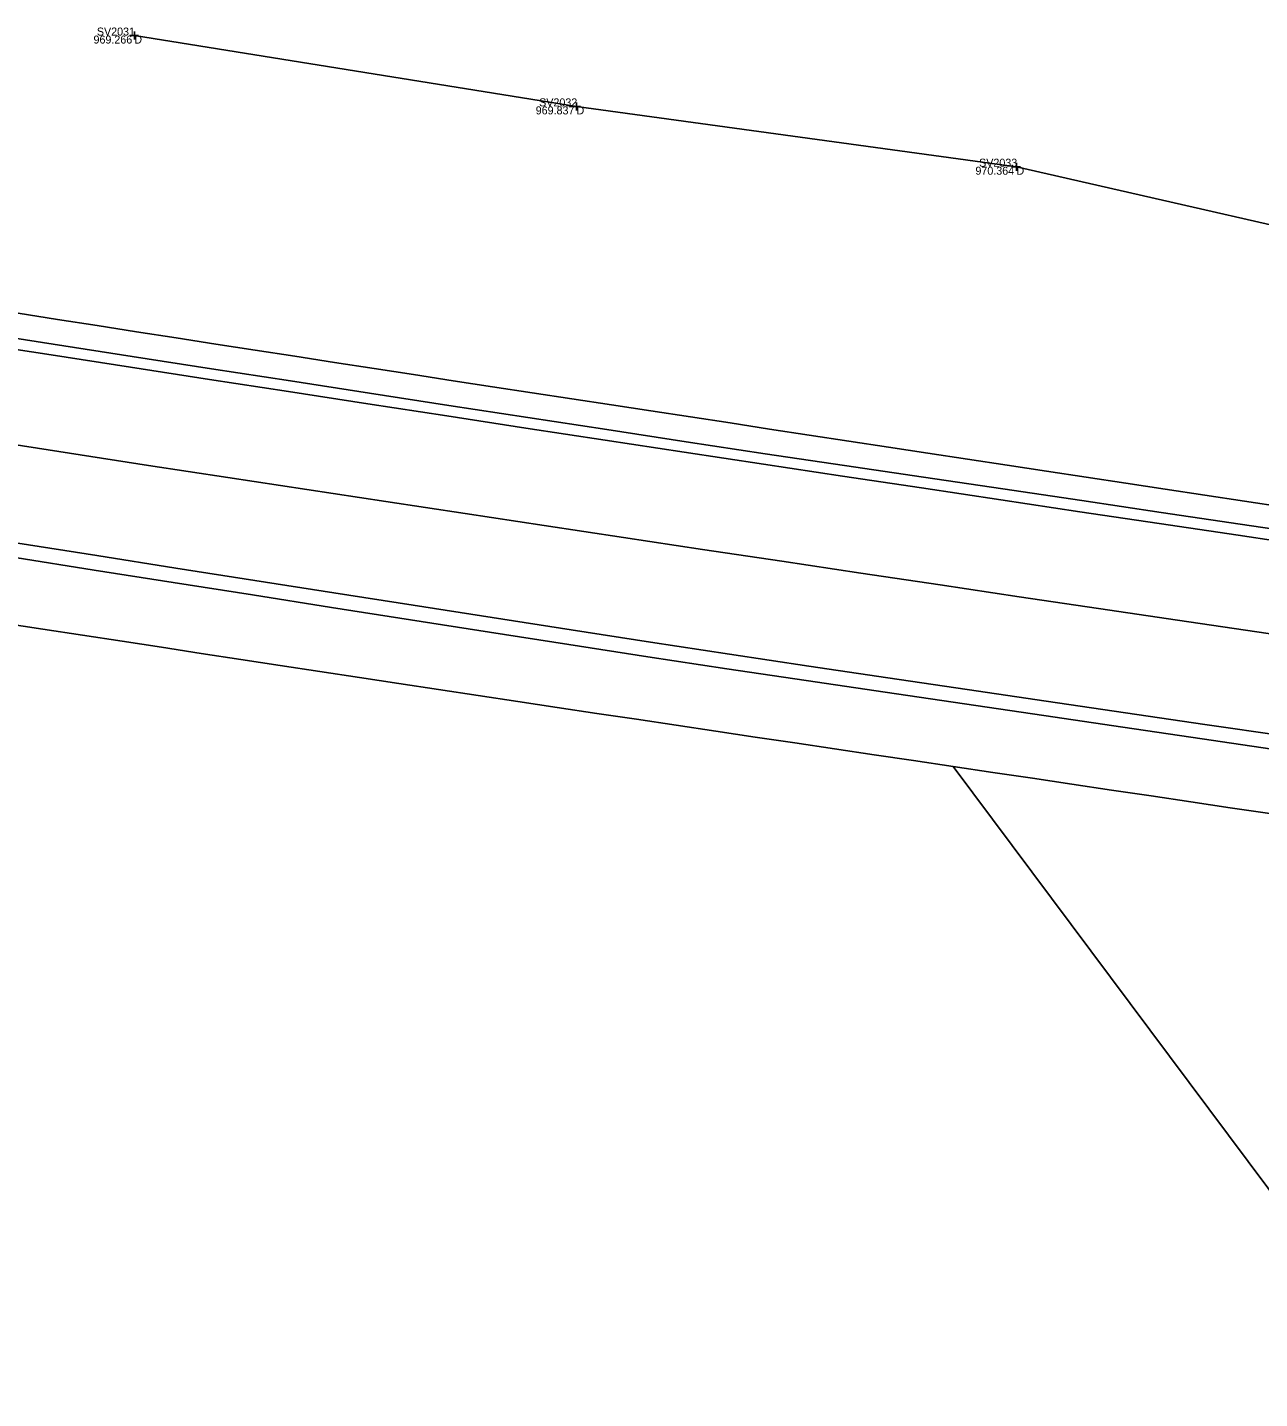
# Model space of a CAD drawing. Extents: x 2065431 to 2068157, y 709104 to 709719.
# Drawn here: x 2066132.9 to 2066286.8, y 709345.9 to 709517.3 of the extents above; entities that cross this region are included whole.
import ezdxf

# ---------------------------------------------------------------- set-up
doc = ezdxf.new("R2010")
doc.units = 0
for name, color, linetype in [('DT_X_Terrain_Boundary', 7, 'Continuous'), ('PM_X_Edge_Line', 7, 'Continuous'), ('PM_X_Lane_Line', 7, 'Continuous'), ('PV_X_EOP', 7, 'Continuous'), ('PV_X_Shoulder_Rumble_Strip', 7, 'Continuous'), ('RS_Raster1', 7, 'Continuous'), ('RW_X_Fee_WL', 7, 'Continuous'), ('SV_X_Mon_Cells_Found', 7, 'Continuous'), ('SV_X_Text_Elevation', 7, 'Continuous'), ('SV_X_Text_Name', 7, 'Continuous')]:
    doc.layers.add(name, color=color, linetype=linetype)

msp = doc.modelspace()

# ---------------------------------------------------------------- linework, layer by layer
at = {"layer": 'DT_X_Terrain_Boundary'}
msp.add_lwpolyline([(2066129.86, 709442.87), (2066134.8, 709442.11), (2066139.74, 709441.35), (2066144.68, 709440.59), (2066149.62, 709439.83), (2066154.57, 709439.07), (2066159.51, 709438.32), (2066164.45, 709437.56), (2066169.4, 709436.81), (2066174.34, 709436.06), (2066179.28, 709435.31), (2066184.23, 709434.56), (2066189.17, 709433.82), (2066194.11, 709433.07), (2066199.06, 709432.33), (2066204, 709431.58), (2066208.95, 709430.84), (2066213.89, 709430.1), (2066218.84, 709429.36), (2066223.78, 709428.62), (2066228.73, 709427.88), (2066233.67, 709427.14), (2066238.62, 709426.4), (2066243.56, 709425.67), (2066248.51, 709424.93), (2066307.45, 709345.95)], dxfattribs=at)
at = {"layer": 'PM_X_Edge_Line'}
for points in [[(2066125.96, 709477.9), (2066135.84, 709476.37), (2066145.72, 709474.83), (2066155.6, 709473.3), (2066165.48, 709471.78), (2066175.37, 709470.26), (2066185.25, 709468.74), (2066195.14, 709467.23), (2066205.02, 709465.73), (2066214.91, 709464.22), (2066224.8, 709462.73), (2066234.69, 709461.23), (2066244.57, 709459.75), (2066254.46, 709458.26), (2066264.35, 709456.78), (2066274.24, 709455.3), (2066284.13, 709453.83), (2066294.02, 709452.36)], [(2066131.65, 709452.85), (2066141.52, 709451.29), (2066151.4, 709449.73), (2066161.28, 709448.18), (2066171.16, 709446.63), (2066181.04, 709445.08), (2066190.92, 709443.54), (2066200.8, 709442), (2066210.68, 709440.47), (2066220.57, 709438.96), (2066230.46, 709437.49), (2066240.35, 709436.03), (2066250.24, 709434.57), (2066260.14, 709433.11), (2066270.03, 709431.65), (2066279.93, 709430.2), (2066289.82, 709428.75)]]:
    msp.add_lwpolyline(points, dxfattribs=at)
at = {"layer": 'PM_X_Lane_Line'}
msp.add_lwpolyline([(2066128.23, 709465.62), (2066138.11, 709464.09), (2066148, 709462.57), (2066157.88, 709461.05), (2066167.77, 709459.54), (2066177.65, 709458.04), (2066187.54, 709456.54), (2066197.43, 709455.04), (2066207.32, 709453.55), (2066217.2, 709452.06), (2066227.09, 709450.58), (2066236.98, 709449.11), (2066246.88, 709447.63), (2066256.77, 709446.16), (2066266.66, 709444.69), (2066276.55, 709443.23), (2066286.44, 709441.77), (2066296.34, 709440.31)], dxfattribs=at)
at = {"layer": 'PV_X_EOP'}
for points in [[(2066131.69, 709481.57), (2066136.63, 709480.8), (2066141.57, 709480.03), (2066146.51, 709479.26), (2066151.45, 709478.49), (2066156.39, 709477.73), (2066161.33, 709476.96), (2066166.27, 709476.2), (2066171.22, 709475.43), (2066176.16, 709474.67), (2066181.1, 709473.91), (2066186.04, 709473.15), (2066190.98, 709472.4), (2066195.93, 709471.64), (2066200.87, 709470.88), (2066205.81, 709470.13), (2066210.75, 709469.38), (2066215.7, 709468.62), (2066220.64, 709467.87), (2066225.58, 709467.11), (2066230.52, 709466.35), (2066235.47, 709465.6), (2066240.41, 709464.84), (2066245.35, 709464.09), (2066250.29, 709463.33), (2066255.24, 709462.58), (2066260.18, 709461.83), (2066265.12, 709461.08), (2066270.07, 709460.33), (2066275.01, 709459.58), (2066279.96, 709458.84), (2066284.9, 709458.09), (2066289.84, 709457.35)], [(2066129.86, 709442.87), (2066134.8, 709442.11), (2066139.74, 709441.35), (2066144.68, 709440.59), (2066149.62, 709439.83), (2066154.57, 709439.07), (2066159.51, 709438.32), (2066164.45, 709437.56), (2066169.4, 709436.81), (2066174.34, 709436.06), (2066179.28, 709435.31), (2066184.23, 709434.56), (2066189.17, 709433.82), (2066194.11, 709433.07), (2066199.06, 709432.33), (2066204, 709431.58), (2066208.95, 709430.84), (2066213.89, 709430.1), (2066218.84, 709429.36), (2066223.78, 709428.62), (2066228.73, 709427.88), (2066233.67, 709427.14), (2066238.62, 709426.4), (2066243.56, 709425.67), (2066248.51, 709424.93), (2066253.45, 709424.19), (2066258.4, 709423.46), (2066263.35, 709422.72), (2066268.29, 709421.99), (2066273.24, 709421.26), (2066278.18, 709420.53), (2066283.13, 709419.79), (2066288.08, 709419.06)]]:
    msp.add_lwpolyline(points, dxfattribs=at)
at = {"layer": 'PV_X_Shoulder_Rumble_Strip'}
for points in [[(2066126.2, 709479.27), (2066136.08, 709477.73), (2066145.96, 709476.19), (2066155.84, 709474.65), (2066165.72, 709473.12), (2066175.61, 709471.59), (2066185.49, 709470.07), (2066195.38, 709468.55), (2066205.26, 709467.04), (2066215.15, 709465.53), (2066225.03, 709464.03), (2066234.92, 709462.56), (2066244.82, 709461.09), (2066254.71, 709459.62), (2066264.6, 709458.16), (2066274.49, 709456.69), (2066284.38, 709455.23), (2066294.28, 709453.77)], [(2066131.32, 709451.04), (2066141.2, 709449.48), (2066151.08, 709447.92), (2066160.96, 709446.37), (2066170.84, 709444.82), (2066180.72, 709443.28), (2066190.6, 709441.74), (2066200.48, 709440.2), (2066210.36, 709438.66), (2066220.25, 709437.15), (2066230.14, 709435.69), (2066240.03, 709434.22), (2066249.92, 709432.76), (2066259.82, 709431.3), (2066269.71, 709429.85), (2066279.6, 709428.39), (2066289.5, 709426.94)]]:
    msp.add_lwpolyline(points, dxfattribs=at)
at = {"layer": 'RS_Raster1'}
for p, q in [((2066145.72, 709516.28), (2066146.72, 709516.28)), ((2066146.22, 709516.78), (2066146.22, 709515.78)), ((2066146.22, 709516.28), (2066146.22, 709516.28)), ((2066200.96, 709507.43), (2066201.96, 709507.43)), ((2066201.46, 709507.93), (2066201.46, 709506.93)), ((2066201.46, 709507.43), (2066201.46, 709507.43)), ((2066256.41, 709500.39), (2066256.41, 709499.39)), ((2066255.91, 709499.89), (2066256.91, 709499.89)), ((2066256.41, 709499.89), (2066256.41, 709499.89))]:
    msp.add_line(p, q, dxfattribs=at)
at = {"layer": 'RW_X_Fee_WL'}
msp.add_lwpolyline([(2066146.22, 709516.28), (2066201.46, 709507.43), (2066256.41, 709499.89), (2066309.66, 709487.73), (2066371.95, 709478.62), (2066434.46, 709468.76), (2066488.47, 709461.11), (2066543.09, 709454.02), (2066597.26, 709445.92), (2066653.85, 709437.6), (2066711.8, 709429.8), (2066769.12, 709422.19), (2066823.53, 709415.48), (2066878.43, 709408.48), (2066947.7, 709399.97)], dxfattribs=at)

# ---------------------------------------------------------------- texts
at = {"layer": 'SV_X_Mon_Cells_Found'}
for s, p in [('SV2031', (2066141.54, 709516.28)), ('SV2032', (2066196.79, 709507.43)), ('SV2033', (2066251.75, 709499.89))]:
    msp.add_text(s, height=1, dxfattribs=at).set_placement(p)
at = {"layer": 'SV_X_Text_Elevation'}
for p in [(2066146.22, 709515.28), (2066201.46, 709506.43), (2066256.41, 709498.89)]:
    msp.add_text('D', height=1, dxfattribs=at).set_placement(p)
at = {"layer": 'SV_X_Text_Name'}
for s, p in [('969.266', (2066141.12, 709515.28)), ('969.837', (2066196.36, 709506.43)), ('970.364', (2066251.29, 709498.89))]:
    msp.add_text(s, height=1, dxfattribs=at).set_placement(p)

doc.saveas('drawing.dxf')
